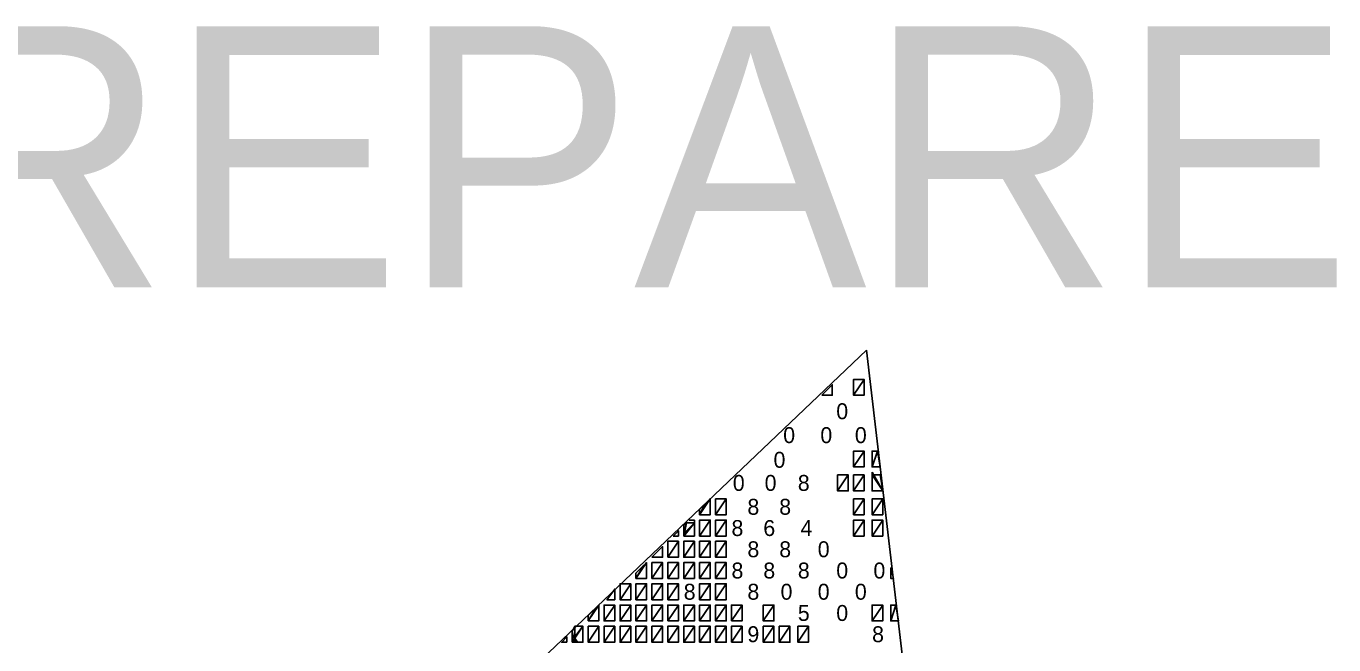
# Model space of a CAD drawing. Extents: x 0 to 44.3, y 0 to 22.
# Drawn here: x 4.338 to 5.039, y 1.361 to 1.693 of the extents above; entities that cross this region are included whole.
import ezdxf

# ---------------------------------------------------------------- set-up
doc = ezdxf.new("R2010")
doc.units = 0
doc.layers.add('Default', color=7, linetype='Continuous')
doc.layers.add('SH_Text', color=7, linetype='Continuous')

msp = doc.modelspace()

# ---------------------------------------------------------------- linework, layer by layer
at = {"layer": 'Default'}
for p, q in [((4.78805, 1.51939), (4.60651, 1.34667)), ((4.78805, 1.51939), (4.81727, 1.27081)), ((4.76976, 1.49519), (4.76976, 1.50088)), ((4.78114, 1.50372), (4.78114, 1.49519)), ((4.78683, 1.49519), (4.78683, 1.50372)), ((4.76976, 1.49519), (4.76407, 1.49519)), ((4.78114, 1.49519), (4.78683, 1.49519)), ((4.78683, 1.46531), (4.78114, 1.46531)), ((4.78114, 1.46531), (4.78114, 1.45678)), ((4.78683, 1.45678), (4.78683, 1.46531)), ((4.7911, 1.46531), (4.79394, 1.46531)), ((4.7911, 1.45678), (4.7911, 1.46531)), ((4.77829, 1.45251), (4.7726, 1.45251)), ((4.7726, 1.45251), (4.7726, 1.44397)), ((4.77829, 1.44397), (4.77829, 1.45251)), ((4.78114, 1.45678), (4.78683, 1.45678)), ((4.78114, 1.45251), (4.78114, 1.44397)), ((4.78683, 1.45251), (4.78114, 1.45251)), ((4.78683, 1.44397), (4.78683, 1.45251)), ((4.7911, 1.45678), (4.79537, 1.45678)), ((4.7911, 1.45251), (4.79537, 1.45251)), ((4.7911, 1.44397), (4.7911, 1.45251)), ((4.70432, 1.43117), (4.70432, 1.43971)), ((4.70717, 1.43971), (4.70717, 1.43117)), ((4.71286, 1.43971), (4.70717, 1.43971)), ((4.71286, 1.43117), (4.71286, 1.43971)), ((4.7726, 1.44397), (4.77829, 1.44397)), ((4.78114, 1.44397), (4.78683, 1.44397)), ((4.78683, 1.43971), (4.78114, 1.43971)), ((4.78114, 1.43971), (4.78114, 1.43117)), ((4.78683, 1.43117), (4.78683, 1.43971)), ((4.7911, 1.44397), (4.79679, 1.44397)), ((4.79679, 1.43971), (4.7911, 1.43971)), ((4.7911, 1.43971), (4.7911, 1.43117)), ((4.79679, 1.43117), (4.79679, 1.43971)), ((4.69863, 1.43117), (4.69863, 1.43402)), ((4.70432, 1.43117), (4.69863, 1.43117)), ((4.70717, 1.43117), (4.71286, 1.43117)), ((4.78114, 1.43117), (4.78683, 1.43117)), ((4.7911, 1.43117), (4.79679, 1.43117)), ((4.69009, 1.41979), (4.69009, 1.42548)), ((4.69578, 1.42832), (4.69294, 1.42832)), ((4.69578, 1.41979), (4.69578, 1.42832)), ((4.70432, 1.42832), (4.69863, 1.42832)), ((4.69863, 1.42832), (4.69863, 1.41979)), ((4.70432, 1.41979), (4.70432, 1.42832)), ((4.71286, 1.42832), (4.70717, 1.42832)), ((4.70717, 1.42832), (4.70717, 1.41979)), ((4.71286, 1.41979), (4.71286, 1.42832)), ((4.78114, 1.42832), (4.78114, 1.41979)), ((4.78683, 1.42832), (4.78114, 1.42832)), ((4.78683, 1.41979), (4.78683, 1.42832)), ((4.7911, 1.42832), (4.7911, 1.41979)), ((4.79679, 1.42832), (4.7911, 1.42832)), ((4.79679, 1.41979), (4.79679, 1.42832)), ((4.68725, 1.41694), (4.68156, 1.41694)), ((4.68156, 1.41694), (4.68156, 1.40841)), ((4.68725, 1.41979), (4.6844, 1.41979)), ((4.68725, 1.41979), (4.68725, 1.42263)), ((4.68725, 1.40841), (4.68725, 1.41694)), ((4.69009, 1.41979), (4.69578, 1.41979)), ((4.69009, 1.41694), (4.69009, 1.40841)), ((4.69578, 1.41694), (4.69009, 1.41694)), ((4.69578, 1.40841), (4.69578, 1.41694)), ((4.69863, 1.41979), (4.70432, 1.41979)), ((4.70432, 1.41694), (4.69863, 1.41694)), ((4.69863, 1.41694), (4.69863, 1.40841)), ((4.70432, 1.40841), (4.70432, 1.41694)), ((4.70717, 1.41979), (4.71286, 1.41979)), ((4.71286, 1.41694), (4.70717, 1.41694)), ((4.70717, 1.41694), (4.70717, 1.40841)), ((4.71286, 1.40841), (4.71286, 1.41694)), ((4.78114, 1.41979), (4.78683, 1.41979)), ((4.7911, 1.41979), (4.79679, 1.41979)), ((4.67871, 1.40841), (4.67871, 1.4141)), ((4.67018, 1.39703), (4.67018, 1.40556)), ((4.67871, 1.40841), (4.67302, 1.40841)), ((4.67302, 1.40556), (4.67302, 1.39703)), ((4.67871, 1.40556), (4.67302, 1.40556)), ((4.67871, 1.39703), (4.67871, 1.40556)), ((4.68156, 1.40841), (4.68725, 1.40841)), ((4.68156, 1.40556), (4.68156, 1.39703)), ((4.68725, 1.40556), (4.68156, 1.40556)), ((4.68725, 1.39703), (4.68725, 1.40556)), ((4.69009, 1.40841), (4.69578, 1.40841)), ((4.69009, 1.40556), (4.69009, 1.39703)), ((4.69578, 1.40556), (4.69009, 1.40556)), ((4.69578, 1.39703), (4.69578, 1.40556)), ((4.69863, 1.40841), (4.70432, 1.40841)), ((4.69863, 1.40556), (4.69863, 1.39703)), ((4.70432, 1.40556), (4.69863, 1.40556)), ((4.70432, 1.39703), (4.70432, 1.40556)), ((4.70717, 1.40841), (4.71286, 1.40841)), ((4.70717, 1.40556), (4.70717, 1.39703)), ((4.71286, 1.40556), (4.70717, 1.40556)), ((4.71286, 1.39703), (4.71286, 1.40556)), ((4.80106, 1.39703), (4.80106, 1.40272)), ((4.67018, 1.39703), (4.66449, 1.39703)), ((4.67302, 1.39703), (4.67871, 1.39703)), ((4.68156, 1.39703), (4.68725, 1.39703)), ((4.69009, 1.39703), (4.69578, 1.39703)), ((4.69863, 1.39703), (4.70432, 1.39703)), ((4.70717, 1.39703), (4.71286, 1.39703)), ((4.80106, 1.39703), (4.80248, 1.39703)), ((4.65311, 1.38565), (4.65311, 1.39134)), ((4.65595, 1.39418), (4.65595, 1.38565)), ((4.66164, 1.39418), (4.65595, 1.39418)), ((4.66164, 1.38565), (4.66164, 1.39418)), ((4.67018, 1.39418), (4.66449, 1.39418)), ((4.66449, 1.39418), (4.66449, 1.38565)), ((4.67018, 1.38565), (4.67018, 1.39418)), ((4.67302, 1.39418), (4.67302, 1.38565)), ((4.67871, 1.39418), (4.67302, 1.39418)), ((4.67871, 1.38565), (4.67871, 1.39418)), ((4.68725, 1.39418), (4.68156, 1.39418)), ((4.68156, 1.39418), (4.68156, 1.38565)), ((4.68725, 1.38565), (4.68725, 1.39418)), ((4.70432, 1.39418), (4.69863, 1.39418)), ((4.69863, 1.39418), (4.69863, 1.38565)), ((4.70432, 1.38565), (4.70432, 1.39418)), ((4.71286, 1.39418), (4.70717, 1.39418)), ((4.70717, 1.39418), (4.70717, 1.38565)), ((4.71286, 1.38565), (4.71286, 1.39418)), ((4.64457, 1.37427), (4.64457, 1.3828)), ((4.64742, 1.3828), (4.64742, 1.37427)), ((4.65311, 1.3828), (4.64742, 1.3828)), ((4.65311, 1.38565), (4.64884, 1.38565)), ((4.65311, 1.37427), (4.65311, 1.3828)), ((4.65595, 1.38565), (4.66164, 1.38565)), ((4.66164, 1.3828), (4.65595, 1.3828)), ((4.65595, 1.3828), (4.65595, 1.37427)), ((4.66164, 1.37427), (4.66164, 1.3828)), ((4.66449, 1.38565), (4.67018, 1.38565)), ((4.66449, 1.3828), (4.66449, 1.37427)), ((4.67018, 1.3828), (4.66449, 1.3828)), ((4.67018, 1.37427), (4.67018, 1.3828)), ((4.67302, 1.38565), (4.67871, 1.38565)), ((4.67871, 1.3828), (4.67302, 1.3828)), ((4.67302, 1.3828), (4.67302, 1.37427)), ((4.67871, 1.37427), (4.67871, 1.3828)), ((4.68156, 1.38565), (4.68725, 1.38565)), ((4.68156, 1.3828), (4.68156, 1.37427)), ((4.68725, 1.3828), (4.68156, 1.3828)), ((4.68725, 1.37427), (4.68725, 1.3828)), ((4.69578, 1.3828), (4.69009, 1.3828)), ((4.69009, 1.3828), (4.69009, 1.37427)), ((4.69578, 1.37427), (4.69578, 1.3828)), ((4.69863, 1.38565), (4.70432, 1.38565)), ((4.69863, 1.3828), (4.69863, 1.37427)), ((4.70432, 1.3828), (4.69863, 1.3828)), ((4.70432, 1.37427), (4.70432, 1.3828)), ((4.70717, 1.38565), (4.71286, 1.38565)), ((4.70717, 1.3828), (4.70717, 1.37427)), ((4.71286, 1.3828), (4.70717, 1.3828)), ((4.71286, 1.37427), (4.71286, 1.3828)), ((4.72139, 1.3828), (4.7157, 1.3828)), ((4.7157, 1.3828), (4.7157, 1.37427)), ((4.72139, 1.37427), (4.72139, 1.3828)), ((4.73277, 1.3828), (4.73277, 1.37427)), ((4.73846, 1.3828), (4.73277, 1.3828)), ((4.73846, 1.37427), (4.73846, 1.3828)), ((4.79679, 1.3828), (4.7911, 1.3828)), ((4.7911, 1.3828), (4.7911, 1.37427)), ((4.79679, 1.37427), (4.79679, 1.3828)), ((4.80106, 1.3828), (4.8039, 1.3828)), ((4.80106, 1.37427), (4.80106, 1.3828)), ((4.63888, 1.37427), (4.63888, 1.37711)), ((4.64457, 1.37427), (4.63888, 1.37427)), ((4.64742, 1.37427), (4.65311, 1.37427)), ((4.65595, 1.37427), (4.66164, 1.37427)), ((4.66449, 1.37427), (4.67018, 1.37427)), ((4.67302, 1.37427), (4.67871, 1.37427)), ((4.68156, 1.37427), (4.68725, 1.37427)), ((4.69009, 1.37427), (4.69578, 1.37427)), ((4.69863, 1.37427), (4.70432, 1.37427)), ((4.70717, 1.37427), (4.71286, 1.37427)), ((4.7157, 1.37427), (4.72139, 1.37427)), ((4.73277, 1.37427), (4.73846, 1.37427)), ((4.7911, 1.37427), (4.79679, 1.37427)), ((4.80106, 1.37427), (4.80532, 1.37427)), ((4.63034, 1.36289), (4.63034, 1.36858)), ((4.63604, 1.37142), (4.63177, 1.37142)), ((4.63604, 1.36289), (4.63604, 1.37142)), ((4.63888, 1.37142), (4.63888, 1.36289)), ((4.64457, 1.37142), (4.63888, 1.37142)), ((4.64457, 1.36289), (4.64457, 1.37142)), ((4.65311, 1.37142), (4.64742, 1.37142)), ((4.64742, 1.37142), (4.64742, 1.36289)), ((4.65311, 1.36289), (4.65311, 1.37142)), ((4.65595, 1.37142), (4.65595, 1.36289)), ((4.66164, 1.37142), (4.65595, 1.37142)), ((4.66164, 1.36289), (4.66164, 1.37142)), ((4.67018, 1.37142), (4.66449, 1.37142)), ((4.66449, 1.37142), (4.66449, 1.36289)), ((4.67018, 1.36289), (4.67018, 1.37142)), ((4.67302, 1.37142), (4.67302, 1.36289)), ((4.67871, 1.37142), (4.67302, 1.37142)), ((4.67871, 1.36289), (4.67871, 1.37142)), ((4.68725, 1.37142), (4.68156, 1.37142)), ((4.68156, 1.37142), (4.68156, 1.36289)), ((4.68725, 1.36289), (4.68725, 1.37142)), ((4.69009, 1.37142), (4.69009, 1.36289)), ((4.69578, 1.37142), (4.69009, 1.37142)), ((4.69578, 1.36289), (4.69578, 1.37142)), ((4.70432, 1.37142), (4.69863, 1.37142)), ((4.69863, 1.37142), (4.69863, 1.36289)), ((4.70432, 1.36289), (4.70432, 1.37142)), ((4.71286, 1.37142), (4.70717, 1.37142)), ((4.70717, 1.37142), (4.70717, 1.36289)), ((4.71286, 1.36289), (4.71286, 1.37142)), ((4.7157, 1.37142), (4.7157, 1.36289)), ((4.72139, 1.37142), (4.7157, 1.37142)), ((4.72139, 1.36289), (4.72139, 1.37142)), ((4.73846, 1.37142), (4.73277, 1.37142)), ((4.73277, 1.37142), (4.73277, 1.36289)), ((4.73846, 1.36289), (4.73846, 1.37142)), ((4.74131, 1.37142), (4.74131, 1.36289)), ((4.747, 1.37142), (4.74131, 1.37142)), ((4.747, 1.36289), (4.747, 1.37142)), ((4.75696, 1.37142), (4.75127, 1.37142)), ((4.75127, 1.37142), (4.75127, 1.36289)), ((4.75696, 1.36289), (4.75696, 1.37142)), ((4.6275, 1.36289), (4.62465, 1.36289)), ((4.63604, 1.36289), (4.63034, 1.36289)), ((4.63888, 1.36289), (4.64457, 1.36289)), ((4.64742, 1.36289), (4.65311, 1.36289)), ((4.65595, 1.36289), (4.66164, 1.36289)), ((4.66449, 1.36289), (4.67018, 1.36289)), ((4.67302, 1.36289), (4.67871, 1.36289)), ((4.68156, 1.36289), (4.68725, 1.36289)), ((4.69009, 1.36289), (4.69578, 1.36289)), ((4.69863, 1.36289), (4.70432, 1.36289)), ((4.70717, 1.36289), (4.71286, 1.36289)), ((4.7157, 1.36289), (4.72139, 1.36289)), ((4.73277, 1.36289), (4.73846, 1.36289)), ((4.74131, 1.36289), (4.747, 1.36289)), ((4.75127, 1.36289), (4.75696, 1.36289))]:
    msp.add_line(p, q, dxfattribs=at)
for points in [[(4.76407, 1.49519), (4.76976, 1.50088), (4.76976, 1.49519)], [(4.78683, 1.50372), (4.78683, 1.49519), (4.78114, 1.49519)], [(4.78114, 1.49519), (4.78114, 1.50372), (4.78683, 1.50372)], [(4.78114, 1.45678), (4.78114, 1.46531), (4.78683, 1.46531)], [(4.78683, 1.46531), (4.78683, 1.45678), (4.78114, 1.45678)], [(4.7911, 1.45678), (4.7911, 1.46531), (4.79394, 1.46531)], [(4.79537, 1.45678), (4.7911, 1.45678), (4.79394, 1.46531)], [(4.7726, 1.44397), (4.7726, 1.45251), (4.77829, 1.45251)], [(4.77829, 1.45251), (4.77829, 1.44397), (4.7726, 1.44397)], [(4.78683, 1.45251), (4.78683, 1.44397), (4.78114, 1.44397)], [(4.78114, 1.44397), (4.78114, 1.45251), (4.78683, 1.45251)], [(4.7911, 1.45393), (4.7911, 1.44397), (4.79679, 1.44397)], [(4.79679, 1.44397), (4.79537, 1.45251), (4.7911, 1.45251)], [(4.69863, 1.43117), (4.70432, 1.43117), (4.70432, 1.43971)], [(4.71286, 1.43971), (4.71286, 1.43117), (4.70717, 1.43117)], [(4.70717, 1.43117), (4.70717, 1.43971), (4.71286, 1.43971)], [(4.78114, 1.43117), (4.78114, 1.43971), (4.78683, 1.43971)], [(4.78683, 1.43971), (4.78683, 1.43117), (4.78114, 1.43117)], [(4.7911, 1.43117), (4.7911, 1.43971), (4.79679, 1.43971)], [(4.79679, 1.43971), (4.79679, 1.43117), (4.7911, 1.43117)], [(4.69863, 1.43117), (4.69863, 1.43402), (4.70147, 1.43686)], [(4.69009, 1.42121), (4.69152, 1.4269), (4.69578, 1.4269)], [(4.69152, 1.4269), (4.69152, 1.4269), (4.69009, 1.42121)], [(4.69009, 1.41979), (4.69009, 1.42548), (4.69152, 1.4269)], [(4.69009, 1.41979), (4.69578, 1.41979), (4.69578, 1.4269)], [(4.69863, 1.41979), (4.70432, 1.41979), (4.70432, 1.42832)], [(4.69863, 1.41979), (4.69863, 1.42832), (4.70432, 1.42832)], [(4.70717, 1.41979), (4.70717, 1.42832), (4.71286, 1.42832)], [(4.71286, 1.42832), (4.71286, 1.41979), (4.70717, 1.41979)], [(4.78683, 1.42832), (4.78683, 1.41979), (4.78114, 1.41979)], [(4.78114, 1.41979), (4.78114, 1.42832), (4.78683, 1.42832)], [(4.79679, 1.42832), (4.79679, 1.41979), (4.7911, 1.41979)], [(4.7911, 1.41979), (4.7911, 1.42832), (4.79679, 1.42832)], [(4.68156, 1.40841), (4.68725, 1.40841), (4.68725, 1.41694)], [(4.68156, 1.40841), (4.68156, 1.41694), (4.68725, 1.41694)], [(4.6844, 1.41979), (4.68725, 1.42263), (4.68725, 1.41979)], [(4.69578, 1.41694), (4.69578, 1.40841), (4.69009, 1.40841)], [(4.69009, 1.40841), (4.69009, 1.41694), (4.69578, 1.41694)], [(4.69863, 1.40841), (4.70432, 1.40841), (4.70432, 1.41694)], [(4.69863, 1.40841), (4.69863, 1.41694), (4.70432, 1.41694)], [(4.70717, 1.40841), (4.70717, 1.41694), (4.71286, 1.41694)], [(4.71286, 1.41694), (4.71286, 1.40841), (4.70717, 1.40841)], [(4.67302, 1.40841), (4.67871, 1.4141), (4.67871, 1.40841)], [(4.66449, 1.39703), (4.67018, 1.40556), (4.67018, 1.39703)], [(4.66449, 1.39703), (4.66449, 1.39987), (4.66876, 1.40414)], [(4.67871, 1.40556), (4.67871, 1.39703), (4.67302, 1.39703)], [(4.67302, 1.39703), (4.67302, 1.40556), (4.67871, 1.40556)], [(4.68156, 1.39703), (4.68725, 1.39703), (4.68725, 1.40556)], [(4.68156, 1.39703), (4.68156, 1.40556), (4.68725, 1.40556)], [(4.69578, 1.40556), (4.69578, 1.39703), (4.69009, 1.39703)], [(4.69009, 1.39703), (4.69009, 1.40556), (4.69578, 1.40556)], [(4.69863, 1.39703), (4.70432, 1.39703), (4.70432, 1.40556)], [(4.69863, 1.39703), (4.69863, 1.40556), (4.70432, 1.40556)], [(4.70717, 1.39703), (4.70717, 1.40556), (4.71286, 1.40556)], [(4.71286, 1.40556), (4.71286, 1.39703), (4.70717, 1.39703)], [(4.80248, 1.39703), (4.80106, 1.39703), (4.80106, 1.40272)], [(4.64884, 1.38565), (4.65311, 1.38565), (4.65311, 1.39134)], [(4.65595, 1.38565), (4.65595, 1.39418), (4.66164, 1.39418)], [(4.66164, 1.39418), (4.66164, 1.38565), (4.65595, 1.38565)], [(4.66164, 1.39418), (4.66164, 1.39418), (4.66164, 1.39418)], [(4.66449, 1.38565), (4.66449, 1.39418), (4.67018, 1.39418)], [(4.67018, 1.39418), (4.67018, 1.38565), (4.66449, 1.38565)], [(4.67871, 1.39418), (4.67871, 1.38565), (4.67302, 1.38565)], [(4.67302, 1.38565), (4.67302, 1.39418), (4.67871, 1.39418)], [(4.68156, 1.38565), (4.68725, 1.38565), (4.68725, 1.39418)], [(4.68156, 1.38565), (4.68156, 1.39418), (4.68725, 1.39418)], [(4.69863, 1.38565), (4.70432, 1.38565), (4.70432, 1.39418)], [(4.69863, 1.38565), (4.69863, 1.39418), (4.70432, 1.39418)], [(4.70717, 1.38565), (4.70717, 1.39418), (4.71286, 1.39418)], [(4.71286, 1.39418), (4.71286, 1.38565), (4.70717, 1.38565)], [(4.63888, 1.37427), (4.64457, 1.37427), (4.64457, 1.3828)], [(4.63888, 1.37427), (4.63888, 1.37711), (4.64315, 1.38138)], [(4.64742, 1.37427), (4.64742, 1.3828), (4.65311, 1.3828)], [(4.65311, 1.3828), (4.65311, 1.37427), (4.64742, 1.37427)], [(4.65311, 1.3828), (4.65311, 1.3828), (4.65311, 1.3828)], [(4.66164, 1.3828), (4.66164, 1.37427), (4.65595, 1.37427)], [(4.65595, 1.37427), (4.65595, 1.3828), (4.66164, 1.3828)], [(4.66164, 1.3828), (4.66164, 1.3828), (4.66164, 1.3828)], [(4.67018, 1.3828), (4.67018, 1.37427), (4.66449, 1.37427)], [(4.66449, 1.37427), (4.66449, 1.3828), (4.67018, 1.3828)], [(4.67302, 1.37427), (4.67302, 1.3828), (4.67871, 1.3828)], [(4.67871, 1.3828), (4.67871, 1.37427), (4.67302, 1.37427)], [(4.68156, 1.37427), (4.68156, 1.3828), (4.68725, 1.3828)], [(4.68156, 1.37427), (4.68725, 1.37427), (4.68725, 1.3828)], [(4.69009, 1.37427), (4.69009, 1.3828), (4.69578, 1.3828)], [(4.69578, 1.3828), (4.69578, 1.37427), (4.69009, 1.37427)], [(4.69863, 1.37427), (4.69863, 1.3828), (4.70432, 1.3828)], [(4.69863, 1.37427), (4.70432, 1.37427), (4.70432, 1.3828)], [(4.71286, 1.3828), (4.71286, 1.37427), (4.70717, 1.37427)], [(4.70717, 1.37427), (4.70717, 1.3828), (4.71286, 1.3828)], [(4.7157, 1.37427), (4.72139, 1.37427), (4.72139, 1.3828)], [(4.7157, 1.37427), (4.7157, 1.3828), (4.72139, 1.3828)], [(4.73277, 1.37427), (4.73277, 1.3828), (4.73846, 1.3828)], [(4.73846, 1.3828), (4.73846, 1.37427), (4.73277, 1.37427)], [(4.73846, 1.3828), (4.73846, 1.3828), (4.73846, 1.3828)], [(4.7911, 1.37427), (4.7911, 1.3828), (4.79679, 1.3828)], [(4.79679, 1.3828), (4.79679, 1.37427), (4.7911, 1.37427)], [(4.80106, 1.37427), (4.80106, 1.3828), (4.8039, 1.3828)], [(4.8039, 1.3828), (4.80532, 1.37427), (4.80106, 1.37427)], [(4.63034, 1.36289), (4.63604, 1.36289), (4.63604, 1.37142)], [(4.63177, 1.36289), (4.63034, 1.36858), (4.63177, 1.37142)], [(4.63177, 1.37142), (4.63604, 1.37142), (4.63177, 1.36573)], [(4.63888, 1.36289), (4.63888, 1.37142), (4.64457, 1.37142)], [(4.64457, 1.37142), (4.64457, 1.36289), (4.63888, 1.36289)], [(4.64457, 1.37142), (4.64457, 1.37142), (4.64457, 1.37142)], [(4.65311, 1.37142), (4.65311, 1.36289), (4.64742, 1.36289)], [(4.64742, 1.36289), (4.64742, 1.37142), (4.65311, 1.37142)], [(4.65311, 1.37142), (4.65311, 1.37142), (4.65311, 1.37142)], [(4.65595, 1.36289), (4.65595, 1.37142), (4.66164, 1.37142)], [(4.66164, 1.37142), (4.66164, 1.36289), (4.65595, 1.36289)], [(4.66164, 1.37142), (4.66164, 1.37142), (4.66164, 1.37142)], [(4.66449, 1.36289), (4.66449, 1.37142), (4.67018, 1.37142)], [(4.67018, 1.37142), (4.67018, 1.36289), (4.66449, 1.36289)], [(4.67871, 1.37142), (4.67871, 1.36289), (4.67302, 1.36289)], [(4.67302, 1.36289), (4.67302, 1.37142), (4.67871, 1.37142)], [(4.68156, 1.36289), (4.68725, 1.36289), (4.68725, 1.37142)], [(4.68156, 1.36289), (4.68156, 1.37142), (4.68725, 1.37142)], [(4.69578, 1.37142), (4.69578, 1.36289), (4.69009, 1.36289)], [(4.69009, 1.36289), (4.69009, 1.37142), (4.69578, 1.37142)], [(4.69863, 1.36289), (4.70432, 1.36289), (4.70432, 1.37142)], [(4.69863, 1.36289), (4.69863, 1.37142), (4.70432, 1.37142)], [(4.70717, 1.36289), (4.70717, 1.37142), (4.71286, 1.37142)], [(4.71286, 1.37142), (4.71286, 1.36289), (4.70717, 1.36289)], [(4.7157, 1.36289), (4.7157, 1.37142), (4.72139, 1.37142)], [(4.7157, 1.36289), (4.72139, 1.36289), (4.72139, 1.37142)], [(4.73846, 1.37142), (4.73846, 1.36289), (4.73277, 1.36289)], [(4.73277, 1.36289), (4.73277, 1.37142), (4.73846, 1.37142)], [(4.73846, 1.37142), (4.73846, 1.37142), (4.73846, 1.37142)], [(4.747, 1.37142), (4.747, 1.36289), (4.74131, 1.36289)], [(4.74131, 1.36289), (4.74131, 1.37142), (4.747, 1.37142)], [(4.75127, 1.36289), (4.75127, 1.37142), (4.75696, 1.37142)], [(4.75696, 1.37142), (4.75696, 1.36289), (4.75127, 1.36289)], [(4.6275, 1.36289), (4.62465, 1.36289), (4.6275, 1.36573)], [(4.63034, 1.36289), (4.63034, 1.36715), (4.63319, 1.36289)]]:
    msp.add_lwpolyline(points, close=True, dxfattribs=at)

# ---------------------------------------------------------------- texts
for s, p in [('0', (4.77189, 1.48238)), ('0', (4.74344, 1.46958)), ('0', (4.76336, 1.46958)), ('0', (4.78185, 1.46958)), ('0', (4.73825, 1.45636)), ('0', (4.71641, 1.44397)), ('0', (4.73348, 1.44397)), ('8', (4.75127, 1.44397)), ('8', (4.72424, 1.43117)), ('8', (4.74131, 1.43117)), ('8', (4.7157, 1.41979)), ('6', (4.73277, 1.41979)), ('4', (4.75269, 1.41979)), ('8', (4.72424, 1.40841)), ('8', (4.74131, 1.40841)), ('0', (4.76194, 1.40841)), ('8', (4.7157, 1.39703)), ('8', (4.73277, 1.39703)), ('8', (4.75127, 1.39703)), ('0', (4.77189, 1.39703)), ('0', (4.79181, 1.39703)), ('8', (4.69009, 1.38565)), ('8', (4.72424, 1.38565)), ('0', (4.74202, 1.38565)), ('0', (4.76194, 1.38565)), ('0', (4.78185, 1.38565)), ('5', (4.75127, 1.37427)), ('0', (4.77189, 1.37427)), ('9', (4.72424, 1.36289)), ('8', (4.7911, 1.36289))]:
    msp.add_text(s, height=0.00854, dxfattribs=at).set_placement(p)
at = {"layer": 'SH_Text'}
msp.add_text('PLAN PREPARED BY:', height=0.14, dxfattribs=at).set_placement((3.61249, 1.55303))

doc.saveas('drawing.dxf')
